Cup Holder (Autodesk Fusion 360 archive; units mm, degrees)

design "Cup Holder" references "Modular Clamp V1"
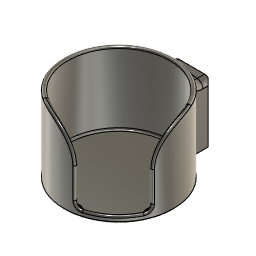
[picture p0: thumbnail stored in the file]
parameter "Cup_Diameter" = 85
parameter "Wall_Thickness" = 3
parameter "Wall_Height" = 60
parameter "Handle_Width" = 20
parameter "Bottom_Thickness" = 5
parameter "Opening_Angle" = 60
parameter "Opening_Tilt" = "-45 grad"
external_derived "ExternalDerived1" bodies "Modular Mount Block Template"
sketch "Sketch1" plane through (0, 0, -20) normal (0, 0, -1) x axis (1, 0, 0)
  line L1 (-2.8284, 69.0858) -> (-15.2071, 56.7071)
  line L2 (15.2071, 56.7071) -> (2.8284, 69.0858)
  line L3 (15.5, 57) -> (15.2071, 56.7071)
  line L4 (15.5, 76.2574) -> (15.5, 57)
  line L5 (-15.5, 76.2574) -> (15.5, 76.2574)
  line L6 (-15.5, 57) -> (-15.5, 76.2574)
  line L7 (-15.2071, 56.7071) -> (-15.5, 57)
  line L8 (15.5, -45.5) -> (-15.5, -45.5)
  line L9 (15.5, -37.1009) -> (15.5, -45.5)
  line L10 (-15.5, -37.1009) -> (15.5, -37.1009)
  line L11 (-15.5, -45.5) -> (-15.5, -37.1009)
  line L12 (0, -45.5) -> (0, -37.1009)
  line L13 (0, -42.5) -> (0, 0)
  line L14 (8.2917, 44.7381) -> (0, 0)
  line L15 (42.8902, 15.1882) -> (0, 0)
  arc A1 centre (0, 66.2574) radius 4 clockwise from (-2.8284, 69.0858) to (2.8284, 69.0858)
  circle C1 centre (0, 0) radius 42.5
  circle C2 centre (0, 0) radius 45.5
  point P1 (0, 0)
  point P11 (0, 0)
  point P17 (0, -37.1009)
  point P18 (0, -45.5)
  point P19 (0, 0)
  point P20 (0, -42.5)
  point P21 (0, 0)
  point P22 (8.2917, 44.7381)
  point P23 (0, 0)
  point P24 (42.8902, 15.1882)
  point P13 (-15.5, -45.5)
  point P14 (15.5, -45.5)
  coincident P1 P11
  horizontal L8
  vertical L9
  horizontal L10
  vertical L11
  tangent C2 L8
  midpoint L10 P17
  midpoint L8 P18
  coincident P11 P19
  coincident C1 P20
  perpendicular L10 L13
  collinear L12 L13
  coincident P1 P21
  coincident C2 P22
  coincident P1 P23
  coincident C2 P24
  dimension "d5" diameter C1 = 85 (= "Cup_Diameter")
  dimension "d6" = 3 (= "Wall_Thickness")
  dimension "d13" distance P13 P14 = 31
  dimension "d31" angle L14 L15 = 60 (= "Opening_Angle")
  dimension "d33" angle L13 L15 = 109.5 (= "180 deg + Opening_Tilt - ( Opening_Angle / 2 )")
extrude "Extrude1" new body sketch "Sketch1" profile of C1 C2 L9 L10 L11 L12 L13 no distance stored bodies "Cup Holder"
extrude "Extrude2" sketch "Sketch1" profile of C1 C2 no distance stored
extrude "Extrude3" add sketch "Sketch1" profile of C2 L8 L9 L11 against normal blind 50
align "Align1"
sketch "Sketch2" plane through (0, 0, -20) normal (0, 0, -1) x axis (1, 0, 0)
  line L1 (-2.8284, -52.6716) -> (-15.2071, -65.0503)
  line L2 (15.2071, -65.0503) -> (2.8284, -52.6716)
  line L3 (15.5, -64.7574) -> (15.2071, -65.0503)
  line L4 (15.5, -45.5) -> (15.5, -64.7574)
  line L5 (-15.5, -45.5) -> (15.5, -45.5)
  line L6 (-15.5, -64.7574) -> (-15.5, -45.5)
  line L7 (-15.2071, -65.0503) -> (-15.5, -64.7574)
  line L8 (-15.5, -51.5) -> (15.5, -51.5)
  arc A1 centre (0, -55.5) radius 4 clockwise from (-2.8284, -52.6716) to (2.8284, -52.6716)
  point P11 (15.5, -51.5)
  point P12 (-15.5, -51.5)
  coincident L4 P11
  coincident L6 P12
  perpendicular L6 L8
  tangent A1 L8
split "Split1" bodies "Modular Mount Block Template (1)"
remove_body "RemoveBody1"
align "Align2"
combine "Combine2" bodies "Modular Mount Block Template"
chamfer "Chamfer1" distance 1
chamfer "Chamfer2" distance 1
extrude "Extrude4" cut sketch "Sketch1" profile of C1 C2 L14 to an object
fillet "Fillet3" radius 30 (= "Wall_Height / 2")
fillet "Fillet4" radius 5
fillet "Fillet5" radius 1.5 (= "Wall_Thickness / 2")
fillet "Fillet6" radius 10 (= "Wall_Height + Bottom_Thickness - 55 mm")
fillet "Fillet7" radius 5
fillet "Fillet8" radius 5
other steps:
derived_base_feature "Derived Base Feature" bodies "Modular Mount Block Template"
named bodies: "Modular Mount Block Template", "Cup Holder", "Modular Mount Block Template (1)"

design "Modular Clamp V1"
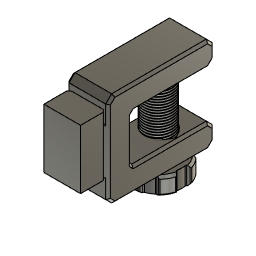
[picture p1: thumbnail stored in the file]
parameter "Thread_Diameter" = 25
parameter "Bolt_Head_Diameter" = 45
parameter "Bolt_Head_Height" = 15
parameter "Clamp_Clearance" = 40
parameter "Clamp_Strenght" = 20
parameter "Clamp_Length" = 70
parameter "Clamp_Thread_Clearance" = 10
parameter "Bolt_Length" = 60 (= "Clamp_Clearance + Clamp_Strenght")
parameter "Thread_Back_Offset" = 30 (= "Clamp_Strenght * 1.5")
parameter "Clamp_Width" = 35 (= "Thread_Diameter + Clamp_Strenght / 2")
parameter "Chamfer_Small" = 2 (= "Clamp_Strenght / 10")
parameter "Chamfer_Large" = 5 (= "Clamp_Strenght / 4")
parameter "Bolt_Chamfer" = 3.125 (= "Thread_Diameter / 8")
parameter "Thread_Tolerance_Additional" = 0.3
parameter "Knurling_Depth" = 3 (= "Bolt_Head_Diameter / 15")
parameter "Knurling_Angle" = 40
parameter "Mount_Strength" = 30
parameter "Mount_Height" = 40 (= "Clamp_Clearance")
parameter "Slot_Undercut" = 8
parameter "Slot_Height" = 20
parameter "Slot_Width" = 30
parameter "Mount_Chamfer_Tolerance" = 1
parameter "Slot_Tolerance" = 0.3
parameter "d157" = 15.5 (= "( Clamp_Width - Chamfer_Small * 2 ) / 2")
sketch "Clamp Side" plane through (0, 0, 0) normal (1, 0, 0) x axis (0, 1, 0)
  line L1 (-35, -20) -> (35, -20)
  line L2 (-35, 20) -> (-35, -20)
  line L3 (35, 20) -> (-35, 20)
  line L4 (35, -20) -> (35, 20)
  line L5 (-35, 20) -> (35, -20)
  line L6 (35, 20) -> (-35, -20)
  line L7 (-55, -40) -> (55, -40)
  line L8 (-55, 40) -> (-55, -40)
  line L9 (55, 40) -> (-55, 40)
  line L10 (55, -40) -> (55, 40)
  line L11 (49.6989, -40) -> (49.6989, 40)
  line L12 (-35, -60) -> (35, -60)
  line L13 (-35, 60) -> (-35, -60)
  line L14 (35, 60) -> (-35, 60)
  line L15 (35, -60) -> (35, 60)
  line L16 (-35, 60) -> (35, -60)
  line L17 (35, 60) -> (-35, -60)
  point P6 (0, 0)
  point P1 (0, 0)
  point P11 (49.6989, 40)
  point P12 (49.6989, -40)
  point P17 (0, 0)
  point P4 (-35, 20)
  point P5 (35, 20)
  point P3 (-35, -20)
  point P15 (-35, 60)
  point P16 (35, 60)
  point P14 (-35, -60)
  horizontal L1
  perpendicular L1 L2
  parallel L1 L3
  parallel L2 L4
  coincident L5 P6
  coincident L6 P6
  coincident P1 P6
  coincident L9 P11
  coincident L7 P12
  perpendicular L7 L11
  horizontal L12
  perpendicular L12 L13
  parallel L12 L14
  parallel L13 L15
  coincident L16 P17
  coincident L17 P17
  coincident P1 P17
  dimension "d8" distance P4 P5 = 70 (= "Clamp_Length")
  dimension "d9" distance P3 P4 = 40 (= "Clamp_Clearance")
  dimension "d21" distance P15 P16 = 70 (= "Clamp_Length")
  dimension "d22" distance P14 P15 = 120 (= "Bolt_Length + Clamp_Strenght * 3")
extrude "Extrude1" new body sketch "Clamp Side" profile of L1 L2 L3 L8 L7 L9 L12 L13 L14 L15 distance 17.5 (= "Clamp_Width / 2")
sketch "Thread and Bolt" plane through (0, 0, -40) normal (0, 0, -1) x axis (1, 0, 0)
  line L1 (17.5, 55) -> (17.5, -35)
  line L2 (-17.5, 55) -> (17.5, 55)
  line L3 (-17.5, -35) -> (-17.5, 55)
  line L4 (17.5, -35) -> (-17.5, -35)
  line L5 (19.5, -5) -> (22.5, -5)
  line L6 (19.0853, -1) -> (19.5, -5)
  line L7 (21.644, 1.147) -> (19.0853, -1)
  line L8 (15.0111, -5) -> (11.2583, 1.5)
  line L9 (19.5, -5) -> (0, -5)
  line L10 (11.2583, -5) -> (0, -5)
  line L11 (1.5, 1.5) -> (11.2583, 1.5)
  line L12 (1.5, -5) -> (1.5, 1.5)
  line L13 (11.2583, -5) -> (1.5, -5)
  line L14 (11.2583, 1.5) -> (11.2583, -5)
  line L15 (15.0111, -5) -> (11.2583, -11.5)
  line L16 (11.2583, -11.5) -> (11.2583, -5)
  line L17 (1.5, -11.5) -> (11.2583, -11.5)
  line L18 (1.5, -5) -> (1.5, -11.5)
  line L19 (5.9587, 43.003) -> (-11.5413, 43.003)
  line L20 (5.9587, 38.003) -> (5.9587, 43.003)
  line L21 (-11.5413, 38.003) -> (5.9587, 38.003)
  line L22 (-12.0413, 42.503) -> (-12.0413, 38.503)
  line L23 (2.4946, 35.3691) -> (2.4946, 45.637)
  line L24 (12.1369, 40.07) -> (3.2446, 34.936)
  line L25 (3.2446, 46.07) -> (12.1369, 40.936)
  circle C1 centre (0, -5) radius 12.5
  circle C2 centre (0, -5) radius 22.5
  circle C3 centre (0, -5) radius 9.375
  circle C4 centre (0, -5) radius 19.5
  circle C5 centre (0, -5) radius 13
  arc A1 centre (2.9946, 45.637) radius 0.5 clockwise from (2.4946, 45.637) to (3.2446, 46.07)
  arc A2 centre (11.8869, 40.503) radius 0.5 clockwise from (12.1369, 40.936) to (12.1369, 40.07)
  arc A3 centre (2.9946, 35.3691) radius 0.5 clockwise from (3.2446, 34.936) to (2.4946, 35.3691)
  arc A4 centre (-11.5413, 42.503) radius 0.5 clockwise from (-12.0413, 42.503) to (-11.5413, 43.003)
  arc A5 centre (-11.5413, 38.503) radius 0.5 clockwise from (-11.5413, 38.003) to (-12.0413, 38.503)
  point P6 (0, -5)
  point P7 (0, -5)
  point P11 (22.5, -5)
  point P12 (19.5, -5)
  point P13 (19.0853, -1)
  point P14 (21.644, 1.147)
  point P8 (0, -5)
  point P16 (0, -5)
  point P15 (15.0111, -5)
  point P17 (0, -5)
  point P20 (11.2583, 1.5)
  point P21 (11.2583, 1.5)
  point P26 (15.0111, -5)
  point P25 (11.2583, -11.5)
  point P28 (11.2583, -11.5)
  point P22 (1.5, 1.5)
  point P29 (1.5, -11.5)
  point P23 (1.5, -5)
  point P30 (1.5, -5)
  point P24 (11.2583, -5)
  point P27 (11.2583, -5)
  point P35 (5.9587, 40.503)
  point P33 (2.4946, 46.503)
  point P34 (2.4946, 34.503)
  point P9 (0, -5)
  coincident P6 P7
  concentric C1 C2
  concentric C2 C3
  coincident C2 P11
  coincident C4 P12
  perpendicular L1 L5
  coincident C4 P13
  coincident C2 P14
  coincident P8 L5
  coincident P8 P16
  coincident P15 L9
  horizontal L10
  coincident P6 P17
  tangent L8 C5
  horizontal L11
  vertical L12
  horizontal L13
  vertical L14
  collinear L9 L13
  coincident P20 P21
  symmetric P15 L9 P26
  symmetric L9 P20 P25
  symmetric L9 P21 P28
  symmetric L9 P22 P29
  symmetric L9 P23 P30
  symmetric L9 P24 P27
  horizontal L19
  vertical L20
  horizontal L21
  vertical L22
  parallel L22 L23
  midpoint L20 P35
  coincident P33 L23
  coincident P33 L25
  tangent L23 A1
  tangent L25 A1
  tangent L24 A2
  tangent L25 A2
  equal A1 A2
  coincident P34 L23
  coincident P34 L24
  tangent L23 A3
  tangent L24 A3
  equal A1 A3
  tangent L19 A4
  tangent L22 A4
  equal A1 A4
  tangent L21 A5
  tangent L22 A5
  equal A1 A5
  dimension "d17" diameter C1 = 25 (= "Thread_Diameter")
  dimension "d23" distance P7 L4 = 30 (= "Thread_Back_Offset")
  dimension "d26" diameter C2 = 45 (= "Bolt_Head_Diameter")
  dimension "d48" diameter C3 = 18.75 (= "Thread_Diameter - Bolt_Chamfer * 2")
  dimension "d55" distance L3 P9 = 17.5 (= "Clamp_Width / 2")
  dimension "d58" angle L5 L7 = 40 (= "Knurling_Angle")
  dimension "d73" angle L8 L9 = 60
  dimension "d80" = 0.5
  dimension "d81" distance P33 P34 = 12
  dimension "d82" radius A1 = 0.5
  dimension "d83" distance L19 L21 = 5
  dimension "d84" distance P33 P35 = 6 (= "d81 / 2")
  dimension "d182" distance P12 P13 = 4
extrude "Extrude2" cut sketch "Thread and Bolt" profile of C1 C3 to an object
thread "Thread1"
extrude "Extrude3" new body sketch "Thread and Bolt" profile of L1 L3 C1 C2 along normal blind 15 (= "Bolt_Head_Height") bodies "Bolt 60 mm"
extrude "Extrude4" new body sketch "Thread and Bolt" profile of C1 no distance stored
combine "Combine1"
chamfer "Chamfer3" distance 2 (= "Chamfer_Small")
thread "Thread2"
offset_faces "OffsetFaces4"
offset_faces "OffsetFaces5"
extrude "Extrude5" new body sketch "Thread and Bolt" profile of C1 C3 no distance stored
chamfer "Chamfer4" distance 3.125 (= "Bolt_Chamfer")
combine "Combine2"
chamfer "Chamfer5" distance 5 (= "Chamfer_Large")
chamfer "Chamfer6" distance 2 (= "Chamfer_Small")
chamfer "Chamfer7" distance 2 (= "Chamfer_Small")
extrude "Extrude6" cut sketch "Thread and Bolt" profile of L1 C2 C4 L5 L7 along normal blind 15 (= "Bolt_Head_Height")
mirror "Mirror1" mirrorStitchTolerance 0.1
fillet "Fillet2" radius 1 (= "Knurling_Depth / 3")
circular_pattern "C-Pattern2" TotalAngle 360
extrude "Extrude7" cut sketch "Thread and Bolt" profile of C1 C3 L8 L9 L10 C5 L11 L13 L14 L15 L16 L17 to an object
sketch "Mount Base" plane through (0, 0, 0) normal (0, 1, 0) x axis (1, 0, 0)
  line L1 (-15.5, 20) -> (15.5, 20)
  line L2 (-15.5, -20) -> (-15.5, 20)
  line L3 (15.5, -20) -> (-15.5, -20)
  line L4 (15.5, 20) -> (15.5, -20)
  line L5 (-15.5, -20) -> (15.5, 20)
  line L6 (15.5, -20) -> (-15.5, 20)
  point P6 (0, 0)
  point P1 (0, 0)
  point P4 (-15.5, -20)
  point P5 (15.5, -20)
  point P3 (-15.5, 20)
  horizontal L1
  perpendicular L1 L2
  parallel L1 L3
  parallel L2 L4
  coincident L5 P6
  coincident L6 P6
  coincident P1 P6
  dimension "d107" distance P4 P5 = 31
  dimension "d108" distance P3 P4 = 40
extrude "Extrude12" sketch "Mount Base" profile of L1 L2 L3 L4 no distance stored
sketch "Mount Profile" plane through (0, 0, -20) normal (0, 0, -1) x axis (1, 0, 0)
  line L1 (0, -22.5) -> (0, -1.75)
  line L2 (15.5, 55) -> (-15.5, 55)
  line L3 (15.5, 85) -> (15.5, 55)
  line L4 (-15.5, 85) -> (15.5, 85)
  line L5 (-15.5, 55) -> (-15.5, 85)
  line L6 (0, 55) -> (0, 85)
  line L7 (-2.1213, 68.3787) -> (-15.5, 55)
  line L8 (5.3866, 55) -> (-15.5, 55)
  line L9 (15.5, 55) -> (2.1213, 68.3787)
  line L10 (15.5, 55) -> (-15.5, 55)
  line L11 (-2.1213, 62.7218) -> (-9.8431, 55)
  line L12 (9.8431, 55) -> (2.1213, 62.7218)
  line L13 (-1.9092, 62.5097) -> (-9.631, 54.7879)
  line L14 (9.631, 54.7879) -> (1.9092, 62.5097)
  line L15 (15.5, 55) -> (-15.5, 55)
  line L16 (15.5, 76.2574) -> (15.5, 55)
  line L17 (-15.5, 76.2574) -> (15.5, 76.2574)
  line L18 (-15.5, 55) -> (-15.5, 76.2574)
  line L19 (12.6716, 52.1716) -> (9.8431, 55)
  line L20 (-12.6716, 52.1716) -> (12.6716, 52.1716)
  line L21 (-9.8431, 55) -> (-12.6716, 52.1716)
  line L22 (17.5, 53) -> (17.5, 49.1716)
  line L23 (15.5, 55) -> (12.6716, 52.1716)
  arc A1 centre (0, 66.2574) radius 3 clockwise from (-2.1213, 68.3787) to (2.1213, 68.3787)
  arc A2 centre (0, 60.6005) radius 3 clockwise from (-2.1213, 62.7218) to (2.1213, 62.7218)
  arc A3 centre (0, 60.6005) radius 2.7 clockwise from (-1.9092, 62.5097) to (1.9092, 62.5097)
  point P8 (0, 85)
  point P9 (0, 55)
  point P4 (-15.5, 55)
  point P10 (-15.5, 55)
  point P5 (15.5, 55)
  point P12 (15.5, 55)
  point P13 (-9.8431, 55)
  point P14 (9.8431, 55)
  point P28 (15.5, 76.2574)
  point P26 (-15.5, 55)
  point P17 (0, 66.2574)
  point P34 (15.5, 55)
  midpoint L4 P8
  midpoint L2 P9
  horizontal L8
  coincident P4 P10
  coincident P5 P12
  coincident L8 P13
  parallel L7 L11
  coincident L2 P14
  parallel L9 L12
  tangent L7 A1
  tangent L9 A1
  tangent L12 A2
  tangent L11 A2
  equal A1 A2
  horizontal L15
  vertical L16
  horizontal L17
  vertical L18
  coincident L3 P28
  coincident P4 P26
  parallel L9 L19
  parallel L15 L20
  parallel L11 L21
  coincident L6 P17
  coincident P5 P34
  dimension "d159" angle L7 L8 = 45
  dimension "d160" distance L7 L11 = 4
  dimension "d162" radius A1 = 3
  dimension "d166" distance P17 L17 = 10
  dimension "d172" distance L9 L12 = 4 (= "d160")
  dimension "d179" angle L20 L23 = 45
extrude "Extrude17" cut sketch "Mount Profile" profile of L2 L3 L4 L5 L6 L7 L9 L10 L11 L12 no distance stored
chamfer "Chamfer16" distance 0.5 distance 10
extrude "Extrude18" new body sketch "Mount Profile" profile of L2 L3 L5 L6 L7 L9 L10 A1 L13 A3 L14 L15 L16 L17 L18 to an object bodies "Modular Mount Block Template"
extrude "Extrude19" sketch "Mount Profile" profile of L2 L3 L5 L6 L7 L9 L10 L11 L12 A1 A2 L13 A3 L14 L15 L16 L17 L18 blind -10
combine "Combine4"
chamfer "Chamfer17" distance 2
chamfer "Chamfer18" distance 2 (= "Chamfer_Small")
chamfer "Chamfer19" distance 1
chamfer "Chamfer20" distance 1
chamfer "Chamfer21" distance 1
chamfer "Chamfer22" distance 1
chamfer "Chamfer23" distance 1
named bodies: "Modular Clamp 40 mm", "Bolt 60 mm", "Modular Mount Block Template"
